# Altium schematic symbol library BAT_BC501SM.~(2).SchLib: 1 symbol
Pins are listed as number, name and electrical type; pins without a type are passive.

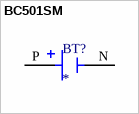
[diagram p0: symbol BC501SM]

## BC501SM
designator BT?
BATTERY HOLDER COIN 12MM SMD; MF: MPD; MP: BC501SM
footprint BAT_BC501SM
pins: N NEG, P POS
